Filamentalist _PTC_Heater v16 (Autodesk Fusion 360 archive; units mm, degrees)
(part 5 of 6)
sketch "Sketch194" plane through (0, 131.7787, 0) normal (0, 1, 0) x axis (-1, 0, 0)
  line L1 (37.9432, -245.7462) -> (-88.2868, -245.7462)
  line L2 (42.9432, -224.8703) -> (42.9432, -240.7462)
  line L3 (45.9432, 73.7538) -> (45.9432, -216.7462)
  line L4 (42.9432, 97.7538) -> (42.9432, 81.8778)
  line L5 (-88.2868, 102.7538) -> (37.9432, 102.7538)
  line L6 (-93.2868, 81.8778) -> (-93.2868, 97.7538)
  line L7 (-96.2868, -216.7462) -> (-96.2868, 73.7538)
  line L8 (-93.2868, -240.7462) -> (-93.2868, -224.8703)
  line L9 (-58.5552, 56.4579) -> (-62.7987, 60.7014)
  line L10 (-62.7986, 22.0143) -> (-58.5552, 26.2578)
  line L11 (-70.3955, 44.8573) -> (-70.3955, 37.8584)
  line L12 (-36.847, 36.1073) -> (-32.5999, 31.8602)
  line L13 (-32.5999, 50.8555) -> (-36.847, 46.6084)
  line L14 (-52.9532, 30.5022) -> (-57.1974, 26.258)
  line L15 (-28.3553, 26.258) -> (-32.5995, 30.5022)
  line L16 (-31.9207, 31.181) -> (-27.6765, 26.9368)
  line L17 (-27.6764, 55.779) -> (-31.9207, 51.5347)
  line L18 (-38.206, 36.1087) -> (-42.7763, 40.6791)
  line L19 (-42.7763, 40.6791) -> (-47.3467, 36.1087)
  line L20 (-57.1975, 56.4578) -> (-52.9532, 52.2135)
  line L21 (-32.5995, 52.2135) -> (-28.3552, 56.4578)
  line L22 (-27.6763, 57.1367) -> (-23.4328, 61.3802)
  line L23 (-62.1199, 61.3802) -> (-57.8764, 57.1367)
  line L24 (-47.3467, 46.607) -> (-42.7763, 42.0366)
  line L25 (-42.7763, 42.0366) -> (-38.206, 46.607)
  line L26 (-52.274, 51.5343) -> (-48.0269, 47.2872)
  line L27 (-37.5258, 47.2872) -> (-33.2787, 51.5343)
  line L28 (-48.0255, 36.7875) -> (-43.4551, 41.3578)
  line L29 (-43.4551, 41.3578) -> (-48.0255, 45.9282)
  line L30 (-52.9528, 31.8602) -> (-48.7057, 36.1073)
  line L31 (-48.7057, 46.6084) -> (-52.9528, 50.8555)
  line L32 (-37.5272, 45.9282) -> (-42.0976, 41.3578)
  line L33 (-42.0976, 41.3578) -> (-37.5272, 36.7875)
  line L34 (-48.0269, 35.4285) -> (-52.274, 31.1814)
  line L35 (-33.2787, 31.1814) -> (-37.5258, 35.4285)
  line L36 (-23.4328, 21.3355) -> (-27.6763, 25.579)
  line L37 (-57.8764, 25.579) -> (-62.1198, 21.3355)
  line L38 (-22.754, 60.7014) -> (-26.9975, 56.4579)
  line L39 (-26.9975, 26.2578) -> (-22.754, 22.0143)
  line L40 (-57.8762, 26.9368) -> (-53.632, 31.181)
  line L41 (-53.632, 51.5347) -> (-57.8763, 55.779)
  line L42 (42.9432, 102.7538) -> (-80.2209, 102.7538)
  line L43 (42.9432, -240.7462) -> (42.9432, 102.7538)
  line L44 (-80.2209, -240.7462) -> (42.9432, -240.7462)
  line L45 (-80.2209, 102.7538) -> (-80.2209, -240.7462)
  line L46 (-96.2868, 89.8158) -> (42.9432, 89.8158)
  line L47 (-96.2868, -204.6678) -> (-96.2868, 89.8158)
  line L48 (42.9432, -204.6678) -> (-96.2868, -204.6678)
  line L49 (42.9432, 89.8158) -> (42.9432, -204.6678)
  line L50 (42.9432, 89.8158) -> (-26.6718, 89.8158)
  line L51 (42.9432, 35.1964) -> (42.9432, 89.8158)
  line L52 (-26.6718, 35.1964) -> (42.9432, 35.1964)
  line L53 (-26.6718, 89.8158) -> (-26.6718, 35.1964)
  line L54 (-96.2868, 89.8158) -> (-26.6718, 89.8158)
  line L55 (-96.2868, 35.1964) -> (-96.2868, 89.8158)
  line L56 (-26.6718, 35.1964) -> (-96.2868, 35.1964)
  line L57 (-26.6718, 89.8158) -> (-26.6718, 35.1964)
  line L58 (74.0902, 102.7538) -> (17.2685, 102.7538)
  line L59 (74.0902, -245.7462) -> (74.0902, 102.7538)
  line L60 (17.2685, -245.7462) -> (74.0902, -245.7462)
  line L61 (17.2685, 102.7538) -> (17.2685, -245.7462)
  line L62 (-160, -71.4962) -> (74.0902, -71.4962)
  line L63 (-160, 150) -> (-160, -71.4962)
  line L64 (74.0902, 150) -> (-160, 150)
  line L65 (74.0902, -71.4962) -> (74.0902, 150)
  line L66 (74.0902, 89.8158) -> (-26.6718, 89.8158)
  line L67 (74.0902, -245.7462) -> (74.0902, 89.8158)
  line L68 (-26.6718, -245.7462) -> (74.0902, -245.7462)
  line L69 (-26.6718, 89.8158) -> (-26.6718, -245.7462)
  line L70 (-107.5093, -236.4962) -> (54.1657, -236.4962)
  line L71 (-107.5093, 93.5038) -> (-107.5093, -236.4962)
  line L72 (54.1657, 93.5038) -> (-107.5093, 93.5038)
  line L73 (54.1657, -236.4962) -> (54.1657, 93.5038)
  line L74 (-107.5093, 93.5038) -> (54.1657, -236.4962)
  line L75 (54.1657, 93.5038) -> (-107.5093, -236.4962)
  line L76 (-75.2868, 93.5038) -> (-93.2868, 93.5038)
  line L77 (-75.2868, 102.7538) -> (-75.2868, 93.5038)
  line L78 (-93.2868, 102.7538) -> (-75.2868, 102.7538)
  line L79 (-93.2868, 93.5038) -> (-93.2868, 102.7538)
  line L80 (24.9432, 93.5038) -> (42.9432, 93.5038)
  line L81 (24.9432, 102.7538) -> (24.9432, 93.5038)
  line L82 (42.9432, 102.7538) -> (24.9432, 102.7538)
  line L83 (42.9432, 93.5038) -> (42.9432, 102.7538)
  line L84 (-75.2868, 93.5038) -> (24.9432, 93.5038)
  line L85 (-75.2868, -306.4962) -> (-75.2868, 93.5038)
  line L86 (24.9432, -306.4962) -> (-75.2868, -306.4962)
  line L87 (24.9432, 93.5038) -> (24.9432, -306.4962)
  arc A1 centre (-88.2868, -240.7462) radius 5 clockwise from (-88.2868, -245.7462) to (-93.2868, -240.7462)
  arc A2 centre (37.9432, -240.7462) radius 5 clockwise from (42.9432, -240.7462) to (37.9432, -245.7462)
  arc A3 centre (47.9432, -224.8703) radius 5 clockwise from (42.9432, -224.8703) to (44.1432, -221.6206)
  arc A4 centre (38.4432, -216.7462) radius 7.5 clockwise from (45.9432, -216.7462) to (44.1432, -221.6206)
  arc A5 centre (38.4432, 73.7538) radius 7.5 clockwise from (44.1432, 78.6282) to (45.9432, 73.7538)
  arc A6 centre (47.9432, 81.8778) radius 5 clockwise from (44.1432, 78.6282) to (42.9432, 81.8778)
  arc A7 centre (37.9432, 97.7538) radius 5 clockwise from (37.9432, 102.7538) to (42.9432, 97.7538)
  arc A8 centre (-88.2868, 97.7538) radius 5 clockwise from (-93.2868, 97.7538) to (-88.2868, 102.7538)
  arc A9 centre (-98.2868, 81.8778) radius 5 clockwise from (-93.2868, 81.8778) to (-94.4868, 78.6282)
  arc A10 centre (-88.7868, 73.7538) radius 7.5 clockwise from (-96.2868, 73.7538) to (-94.4868, 78.6282)
  arc A11 centre (-88.7868, -216.7462) radius 7.5 clockwise from (-94.4868, -221.6206) to (-96.2868, -216.7462)
  arc A12 centre (-98.2868, -224.8703) radius 5 clockwise from (-94.4868, -221.6206) to (-93.2868, -224.8703)
  circle C1 centre (3.265, 1.258) radius 1.1
  circle C2 centre (-24.3297, -214.0862) radius 3.175
  circle C3 centre (-32.1307, -209.6412) radius 3.175
  circle C4 centre (-39.8297, -214.0862) radius 3.175
  circle C5 centre (-24.4318, -205.1962) radius 3.175
  circle C6 centre (-16.7002, -209.6409) radius 3.175
  circle C7 centre (-39.8297, -205.1962) radius 3.175
  circle C8 centre (-24.4318, -196.3062) radius 3.175
  circle C9 centre (-39.8297, -196.3062) radius 3.175
  circle C10 centre (-55.1992, -205.1959) radius 3.175
  circle C11 centre (-47.5287, -182.9712) radius 3.175
  circle C12 centre (-32.1023, -182.9709) radius 3.175
  circle C13 centre (-47.5287, -191.8612) radius 3.175
  circle C14 centre (-62.8982, -200.7509) radius 3.175
  circle C15 centre (-70.6297, -187.4162) radius 3.175
  circle C16 centre (-55.1992, -178.5259) radius 3.175
  circle C17 centre (-39.8013, -169.6359) radius 3.175
  circle C18 centre (-55.1992, -169.6359) radius 3.175
  circle C19 centre (-78.3287, -182.9712) radius 3.175
  circle C20 centre (-78.3287, -165.1912) radius 3.175
  circle C21 centre (-78.3287, -174.0812) radius 3.175
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  point P6 (42.9432, -240.7462)
  point P356 (42.9432, -240.7462)
  point P354 (-80.2209, 102.7538)
  point P360 (-96.2868, -204.6678)
  point P358 (42.9432, 89.8158)
  point P364 (42.9432, 35.1964)
  point P362 (-26.6718, 89.8158)
  point P367 (-96.2868, 35.1964)
  point P369 (17.2685, 102.7538)
  point P373 (74.0902, -71.4962)
  point P383 (-26.6718, -71.4962)
  point P384 (-93.2868, 93.5038)
  point P388 (42.9432, 93.5038)
  point P392 (-75.2868, 93.5038)
  point P395 (-75.2868, 93.5038)
  point P389 (24.9432, 93.5038)
  point P396 (24.9432, 93.5038)
  point P397 (-75.2868, -236.4962)
  point P398 (24.9432, -236.4962)
  point P380 (-107.5093, -236.4962)
  point P381 (-107.5093, 93.5038)
  point P385 (-75.2868, 93.5038)
  point P394 (24.9432, -306.4962)
  horizontal L42
  vertical L43
  horizontal L44
  vertical L45
  coincident P6 P356
  coincident L5 P354
  horizontal L46
  vertical L47
  horizontal L48
  vertical L49
  coincident L7 P360
  midpoint L4 P358
  horizontal L50
  vertical L51
  horizontal L52
  vertical L53
  coincident L43 P364
  midpoint L46 P362
  horizontal L54
  vertical L55
  horizontal L56
  vertical L57
  coincident L47 P367
  horizontal L58
  vertical L59
  horizontal L60
  vertical L61
  coincident L42 P369
  horizontal L62
  vertical L63
  horizontal L64
  vertical L65
  midpoint L59 P373
  horizontal L66
  vertical L67
  horizontal L68
  vertical L69
  horizontal L70
  perpendicular L70 L71
  parallel L70 L72
  parallel L71 L73
  coincident L74 P383
  coincident L75 P383
  coincident L62 P383
  coincident L69 P383
  horizontal L76
  vertical L77
  horizontal L78
  vertical L79
  coincident L72 P384
  coincident L6 P384
  horizontal L80
  vertical L81
  horizontal L82
  vertical L83
  coincident L43 P388
  coincident L72 P388
  horizontal L84
  vertical L85
  horizontal L86
  vertical L87
  coincident P392 P395
  coincident P389 P396
  coincident L85 P397
  coincident L70 P397
  coincident L87 P398
  coincident L70 P398
  dimension "d619" distance P380 P381 = 330
  dimension "d620" distance P384 P385 = 18
  dimension "d621" distance P388 P389 = 18
  dimension "d622" distance P389 P394 = 400
  dimension "d623" diameter = 5.4
  dimension "d624" diameter = 5.4
  dimension "d625" diameter = 5.4
  dimension "d626" diameter = 5.4
extrude "Extrude55" cut sketch "Sketch194" against normal blind 50
position "Position14"
sketch "Sketch195" plane through (0, 131.7787, 0) normal (0, 1, 0) x axis (-1, 0, 0)
  line L1 (37.9432, -245.7462) -> (-88.2868, -245.7462)
  line L2 (42.9432, -224.8703) -> (42.9432, -240.7462)
  line L3 (45.9432, 73.7538) -> (45.9432, -216.7462)
  line L4 (42.9432, 97.7538) -> (42.9432, 81.8778)
  line L5 (-88.2868, 102.7538) -> (37.9432, 102.7538)
  line L6 (-93.2868, 81.8778) -> (-93.2868, 97.7538)
  line L7 (-96.2868, -216.7462) -> (-96.2868, 73.7538)
  line L8 (-93.2868, -240.7462) -> (-93.2868, -224.8703)
  line L9 (-58.5552, 56.4579) -> (-62.7987, 60.7014)
  line L10 (-62.7986, 22.0143) -> (-58.5552, 26.2578)
  line L11 (-70.3955, 44.8573) -> (-70.3955, 37.8584)
  line L12 (-36.847, 36.1073) -> (-32.5999, 31.8602)
  line L13 (-32.5999, 50.8555) -> (-36.847, 46.6084)
  line L14 (-52.9532, 30.5022) -> (-57.1974, 26.258)
  line L15 (-28.3553, 26.258) -> (-32.5995, 30.5022)
  line L16 (-31.9207, 31.181) -> (-27.6765, 26.9368)
  line L17 (-27.6764, 55.779) -> (-31.9207, 51.5347)
  line L18 (-38.206, 36.1087) -> (-42.7763, 40.6791)
  line L19 (-42.7763, 40.6791) -> (-47.3467, 36.1087)
  line L20 (-57.1975, 56.4578) -> (-52.9532, 52.2135)
  line L21 (-32.5995, 52.2135) -> (-28.3552, 56.4578)
  line L22 (-27.6763, 57.1367) -> (-23.4328, 61.3802)
  line L23 (-62.1199, 61.3802) -> (-57.8764, 57.1367)
  line L24 (-47.3467, 46.607) -> (-42.7763, 42.0366)
  line L25 (-42.7763, 42.0366) -> (-38.206, 46.607)
  line L26 (-52.274, 51.5343) -> (-48.0269, 47.2872)
  line L27 (-37.5258, 47.2872) -> (-33.2787, 51.5343)
  line L28 (-48.0255, 36.7875) -> (-43.4551, 41.3578)
  line L29 (-43.4551, 41.3578) -> (-48.0255, 45.9282)
  line L30 (-52.9528, 31.8602) -> (-48.7057, 36.1073)
  line L31 (-48.7057, 46.6084) -> (-52.9528, 50.8555)
  line L32 (-37.5272, 45.9282) -> (-42.0976, 41.3578)
  line L33 (-42.0976, 41.3578) -> (-37.5272, 36.7875)
  line L34 (-48.0269, 35.4285) -> (-52.274, 31.1814)
  line L35 (-33.2787, 31.1814) -> (-37.5258, 35.4285)
  line L36 (-23.4328, 21.3355) -> (-27.6763, 25.579)
  line L37 (-57.8764, 25.579) -> (-62.1198, 21.3355)
  line L38 (-22.754, 60.7014) -> (-26.9975, 56.4579)
  line L39 (-26.9975, 26.2578) -> (-22.754, 22.0143)
  line L40 (-57.8762, 26.9368) -> (-53.632, 31.181)
  line L41 (-53.632, 51.5347) -> (-57.8763, 55.779)
  line L42 (38.4432, -217.5) -> (-85, -217.5)
  line L43 (-85, 73.7538) -> (38.4432, 73.7538)
  line L44 (24.9432, 93.5038) -> (-75.2868, 93.5038)
  line L45 (24.9432, 82.1771) -> (24.9432, 93.5038)
  line L46 (-75.2868, 82.1771) -> (24.9432, 82.1771)
  line L47 (-75.2868, 93.5038) -> (-75.2868, 82.1771)
  line L48 (-0.8286, 73.7538) -> (-85, 73.7538)
  line L49 (-85, 73.7538) -> (-85, 1.258)
  line L50 (38.4432, -124.7165) -> (-85, -124.7165)
  line L51 (38.4432, -217.5) -> (38.4432, -124.7165)
  line L52 (-85, -217.5) -> (38.4432, -217.5)
  line L53 (-85, -124.7165) -> (-85, -217.5)
  line L54 (-89, 73.7538) -> (-85, 73.7538)
  line L55 (-89, 77.7538) -> (-89, 73.7538)
  line L56 (-85, 77.7538) -> (-89, 77.7538)
  line L57 (-85, 73.7538) -> (-85, 77.7538)
  line L58 (42.4432, -221.5) -> (42.4432, -217.5)
  line L59 (38.4432, -221.5) -> (42.4432, -221.5)
  line L60 (42.4432, 77.7538) -> (-89, 77.7538)
  line L61 (42.4432, -221.5) -> (42.4432, 77.7538)
  line L62 (-89, -221.5) -> (42.4432, -221.5)
  line L63 (-89, 77.7538) -> (-89, -221.5)
  line L64 (38.4432, -124.7165) -> (-85, -124.7165)
  line L65 (-85, -120.7165) -> (38.4432, -120.7165)
  line L66 (-85, 1.258) -> (-85, 5.258)
  line L67 (-4.8286, 73.7538) -> (-0.8286, 73.7538)
  line L68 (-85, -120.7165) -> (-85, 73.7538)
  line L69 (-85, -217.5) -> (-85, -124.7165)
  line L70 (38.4432, -124.7165) -> (38.4432, -217.5)
  line L71 (38.4432, 73.7538) -> (38.4432, -120.7165)
  line L72 (-67.7764, 66.3578) -> (-17.7763, 66.3578)
  line L73 (-67.7764, 16.3579) -> (-67.7764, 66.3578)
  line L74 (-17.7763, 16.3579) -> (-67.7764, 16.3579)
  line L75 (-17.7763, 66.3578) -> (-17.7763, 16.3579)
  line L76 (-67.7764, 16.3579) -> (-17.7763, 66.3578)
  line L77 (-17.7763, 16.3579) -> (-67.7764, 66.3578)
  line L78 (-85, 73.7538) -> (-4.8286, 73.7538)
  line L79 (-85, 5.258) -> (-85, 73.7538)
  line L80 (-4.8286, 5.258) -> (-85, 5.258)
  line L81 (-4.8286, 73.7538) -> (-4.8286, 5.258)
  line L82 (-85, 73.7538) -> (-0.8286, 73.7538)
  line L83 (-85, 1.258) -> (-85, 73.7538)
  line L84 (-0.8286, 1.258) -> (-85, 1.258)
  line L85 (-0.8286, 73.7538) -> (-0.8286, 1.258)
  circle C1 centre (-75.2868, -236.4962) radius 2.7
  circle C2 centre (-75.2868, 93.5038) radius 2.7
  circle C3 centre (24.9432, -236.4962) radius 2.7
  circle C4 centre (24.9432, 93.5038) radius 2.7
  arc A1 centre (-88.2868, -240.7462) radius 5 clockwise from (-88.2868, -245.7462) to (-93.2868, -240.7462)
  arc A2 centre (37.9432, -240.7462) radius 5 clockwise from (42.9432, -240.7462) to (37.9432, -245.7462)
  arc A3 centre (47.9432, -224.8703) radius 5 clockwise from (42.9432, -224.8703) to (44.1432, -221.6206)
  arc A4 centre (38.4432, -216.7462) radius 7.5 clockwise from (45.9432, -216.7462) to (44.1432, -221.6206)
  arc A5 centre (38.4432, 73.7538) radius 7.5 clockwise from (44.1432, 78.6282) to (45.9432, 73.7538)
  arc A6 centre (47.9432, 81.8778) radius 5 clockwise from (44.1432, 78.6282) to (42.9432, 81.8778)
  arc A7 centre (37.9432, 97.7538) radius 5 clockwise from (37.9432, 102.7538) to (42.9432, 97.7538)
  arc A8 centre (-88.2868, 97.7538) radius 5 clockwise from (-93.2868, 97.7538) to (-88.2868, 102.7538)
  arc A9 centre (-98.2868, 81.8778) radius 5 clockwise from (-93.2868, 81.8778) to (-94.4868, 78.6282)
  arc A10 centre (-88.7868, 73.7538) radius 7.5 clockwise from (-96.2868, 73.7538) to (-94.4868, 78.6282)
  arc A11 centre (-88.7868, -216.7462) radius 7.5 clockwise from (-94.4868, -221.6206) to (-96.2868, -216.7462)
  arc A12 centre (-98.2868, -224.8703) radius 5 clockwise from (-94.4868, -221.6206) to (-93.2868, -224.8703)
  circle C5 centre (3.265, 1.258) radius 1.1
  circle C6 centre (-24.3297, -214.0862) radius 3.175
  circle C7 centre (-32.1307, -209.6412) radius 3.175
  circle C8 centre (-39.8297, -214.0862) radius 3.175
  circle C9 centre (-24.4318, -205.1962) radius 3.175
  circle C10 centre (-16.7002, -209.6409) radius 3.175
  circle C11 centre (-39.8297, -205.1962) radius 3.175
  circle C12 centre (-24.4318, -196.3062) radius 3.175
  circle C13 centre (-39.8297, -196.3062) radius 3.175
  circle C14 centre (-55.1992, -205.1959) radius 3.175
  circle C15 centre (-47.5287, -182.9712) radius 3.175
  circle C16 centre (-32.1023, -182.9709) radius 3.175
  circle C17 centre (-47.5287, -191.8612) radius 3.175
  circle C18 centre (-62.8982, -200.7509) radius 3.175
  circle C19 centre (-70.6297, -187.4162) radius 3.175
  circle C20 centre (-55.1992, -178.5259) radius 3.175
  circle C21 centre (-39.8013, -169.6359) radius 3.175
  circle C22 centre (-55.1992, -169.6359) radius 3.175
  circle C23 centre (-78.3287, -182.9712) radius 3.175
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  point P19 (38.4432, 73.7538)
  point P360 (38.4432, 73.7538)
  point P3 (-75.2868, 93.5038)
  point P362 (-75.2868, 93.5038)
  point P368 (-85, -124.7165)
  point P390 (-42.7763, 41.3579)
  point P310 (-17.7763, 66.3578)
  point P386 (-17.7763, 66.3578)
  point P385 (-42.7763, 41.3579)
  point P391 (-17.7763, 66.3578)
  point P389 (-17.7763, 16.3579)
  point P392 (-17.7763, 16.3579)
  point P388 (-67.7764, 16.3579)
  point P393 (-67.7764, 16.3579)
  point P396 (-17.7763, 16.3579)
  point P361 (-85, 73.7538)
  point P371 (-89, 73.7538)
  point P373 (-85, 77.7538)
  point P359 (38.4432, -217.5)
  point P374 (42.4432, -217.5)
  point P376 (38.4432, -221.5)
  point P381 (-85, -120.7165)
  point P367 (-85, 1.258)
  point P382 (-85, 5.258)
  point P366 (-0.8286, 73.7538)
  point P383 (-4.8286, 73.7538)
  horizontal L42
  vertical L70
  horizontal L43
  vertical L68
  coincident P19 P360
  horizontal L44
  vertical L45
  horizontal L46
  vertical L47
  coincident P3 P362
  horizontal L48
  vertical L49
  horizontal L50
  vertical L51
  horizontal L52
  vertical L53
  coincident P368 L68
  horizontal L54
  vertical L55
  horizontal L56
  vertical L57
  vertical L58
  horizontal L59
  horizontal L60
  vertical L61
  horizontal L62
  vertical L63
  horizontal L64
  horizontal L65
  vertical L66
  horizontal L67
  collinear L68 L69
  collinear L70 L71
  horizontal L72
  perpendicular L72 L73
  parallel L72 L74
  parallel L73 L75
  coincident L76 P390
  coincident L77 P390
  coincident P310 P386
  coincident P385 P390
  coincident P386 P391
  coincident P389 P392
  coincident P388 P393
  coincident P389 P396
  horizontal L78
  vertical L79
  horizontal L80
  vertical L81
  horizontal L82
  vertical L83
  horizontal L84
  vertical L85
  dimension "d629" distance P361 P371 = 4
  dimension "d630" distance P361 P373 = 4
  dimension "d631" distance P359 P374 = 4
  dimension "d632" distance P359 P376 = 4
  dimension "d633" distance P368 P381 = 4
  dimension "d634" distance P367 P382 = 4
  dimension "d635" distance P366 P383 = 4
  dimension "d636" diameter = 8.4
  dimension "d637" diameter = 8.4
  dimension "d638" diameter = 8.4
  dimension "d639" diameter = 8.4
extrude "Extrude59" new body sketch "Sketch195" along normal blind 7.5
delete_face "DeleteFace2"
fillet "Fillet2" radius 10
fillet "Fillet3" radius 5
fillet "Fillet4" radius 12
fillet "Fillet5" radius 10
sketch "Sketch196" plane through (0, 139.2787, 0) normal (0, 1, 0) x axis (-1, 0, 0)
  line L1 (-0.8286, 63.7538) -> (-0.8286, 13.258)
  line L2 (28.4432, 73.7538) -> (9.1714, 73.7538)
  line L3 (38.4432, -110.7165) -> (38.4432, 63.7538)
  line L4 (-75, -120.7165) -> (28.4432, -120.7165)
  line L5 (-85, -8.742) -> (-85, -110.7165)
  line L6 (-12.8286, 1.258) -> (-75, 1.258)
  line L7 (-85, -134.7165) -> (-85, -207.5)
  line L8 (28.4432, -124.7165) -> (-75, -124.7165)
  line L9 (38.4432, -207.5) -> (38.4432, -134.7165)
  line L10 (-75, -217.5) -> (28.4432, -217.5)
  line L11 (-14.8286, 73.7538) -> (-75, 73.7538)
  line L12 (-4.8286, 15.258) -> (-4.8286, 63.7538)
  line L13 (-75, 5.258) -> (-14.8286, 5.258)
  line L14 (-85, 63.7538) -> (-85, 15.258)
  line L15 (37.4432, -221.5) -> (-84, -221.5)
  line L16 (42.4432, 72.7538) -> (42.4432, -216.5)
  line L17 (-84, 77.7538) -> (37.4432, 77.7538)
  line L18 (-89, -216.5) -> (-89, 72.7538)
  line L19 (28.4432, 77.7538) -> (19.4287, 77.7538)
  line L20 (28.4432, 73.7538) -> (28.4432, 77.7538)
  line L21 (19.4287, 73.7538) -> (28.4432, 73.7538)
  line L22 (19.4287, 77.7538) -> (19.4287, 73.7538)
  line L23 (42.4432, 57.2957) -> (38.4432, 57.2957)
  line L24 (42.4432, 48.2332) -> (42.4432, 57.2957)
  line L25 (38.4432, 48.2332) -> (42.4432, 48.2332)
  line L26 (38.4432, 57.2957) -> (38.4432, 48.2332)
  line L27 (-65, -217.5) -> (-71, -217.5)
  line L28 (-65, -221.5) -> (-65, -217.5)
  line L29 (-71, -221.5) -> (-65, -221.5)
  line L30 (-71, -217.5) -> (-71, -221.5)
  line L31 (-85, -201) -> (-89, -201)
  line L32 (-85, -207) -> (-85, -201)
  line L33 (-89, -207) -> (-85, -207)
  line L34 (-89, -201) -> (-89, -207)
  line L35 (-63.4732, -120.7165) -> (-70.1474, -120.7165)
  line L36 (-63.4732, -124.7165) -> (-63.4732, -120.7165)
  line L37 (-70.1474, -124.7165) -> (-63.4732, -124.7165)
  line L38 (-70.1474, -120.7165) -> (-70.1474, -124.7165)
  line L39 (-46.3683, 5.258) -> (-55.4988, 5.258)
  line L40 (-46.3683, 1.258) -> (-46.3683, 5.258)
  line L41 (-55.4988, 1.258) -> (-46.3683, 1.258)
  line L42 (-55.4988, 5.258) -> (-55.4988, 1.258)
  line L43 (40.4432, 75.7538) -> (19.4287, 75.7538)
  line L44 (40.4432, 57.2957) -> (40.4432, 75.7538)
  line L45 (19.4287, 57.2957) -> (40.4432, 57.2957)
  line L46 (19.4287, 75.7538) -> (19.4287, 57.2957)
  line L47 (-71, -201) -> (-87, -201)
  line L48 (-71, -219.5) -> (-71, -201)
  line L49 (-87, -219.5) -> (-71, -219.5)
  line L50 (-87, -201) -> (-87, -219.5)
  line L51 (40.4432, -219.5) -> (-87, -219.5)
  line L52 (40.4432, 75.7538) -> (40.4432, -219.5)
  line L53 (-87, 75.7538) -> (40.4432, 75.7538)
  line L54 (-87, -219.5) -> (-87, 75.7538)
  line L55 (-46.3683, 75.7538) -> (-87, 75.7538)
  line L56 (-46.3683, 3.258) -> (-46.3683, 75.7538)
  line L57 (-87, 75.7538) -> (-87, 3.258)
  line L58 (-87, -115) -> (-87, -122.7165)
  line L59 (-70.1474, -115) -> (-87, -115)
  line L60 (-70.1474, -122.7165) -> (-70.1474, -115)
  line L61 (40.4432, -178.5523) -> (40.4432, -122.7165)
  line L62 (-87, -178.5523) -> (40.4432, -178.5523)
  line L63 (-87, -122.7165) -> (-87, -178.5523)
  line L64 (28.443, 63.753) -> (-75.0066, 63.753)
  line L65 (-2.8286, 77.7538) -> (-2.8286, 63.753)
  line L66 (40.4432, -122.7165) -> (28.4432, -110.7166)
  line L67 (28.4432, -134.7166) -> (40.4432, -122.7165)
  line L68 (-87, -122.7165) -> (-74.9306, -111.1407)
  line L69 (-87, -122.7165) -> (-75.0091, -135.3352)
  line L70 (-83.3532, 72.138) -> (-74.9907, 63.7704)
  line L71 (-84, 75.7538) -> (-87, 75.7538)
  line L72 (-84, 74.9011) -> (-84, 75.7538)
  line L73 (-87, 72.7538) -> (-86.1057, 72.7538)
  line L74 (-87, 75.7538) -> (-87, 72.7538)
  line L75 (37.4432, -219.5) -> (40.4432, -219.5)
  line L76 (40.4432, -219.5) -> (40.4432, -216.5)
  line L77 (36.9309, -218.4885) -> (28.4432, -210.0013)
  line L78 (36.7873, -218.3449) -> (28.4432, -210.0013)
  line L79 (37.9893, 73.3188) -> (-82.8642, 73.3188)
  line L80 (-82.8529, -219.547) -> (36.2894, -219.547)
  line L81 (40.4432, -122.7165) -> (38.6285, -122.7165)
  line L82 (37.9893, -121.3894) -> (37.9893, 73.3188)
  line L83 (37.9893, -217.847) -> (37.9893, -124.0462)
  line L84 (36.9285, -121.0178) -> (36.9285, -119.2018)
  line L85 (36.9285, -126.2313) -> (36.9285, -124.4178)
  line L86 (-85.1919, -122.7165) -> (-87, -122.7165)
  line L87 (35.2285, -122.7165) -> (-81.7939, -122.7165)
  line L88 (-84.5529, -123.9864) -> (-84.5529, -217.8469)
  line L89 (-81.7939, -122.7165) -> (-70.1474, -122.7165)
  line L90 (-87, -122.7165) -> (-85.1919, -122.7165)
  line L91 (-83.4529, -120.9578) -> (-83.4134, -119.2766)
  line L92 (-83.5789, -126.3167) -> (-83.5329, -124.3568)
  line L93 (-85.7308, 74.4837) -> (-87, 75.7538)
  line L94 (-75.0066, 63.753) -> (-83.37, 72.1215)
  line L95 (-82.8528, 3.258) -> (-46.3683, 3.258)
  line L96 (-87, 3.258) -> (-86.2528, 3.258)
  line L97 (-84.5529, 1.558) -> (-84.5529, -121.3282)
  line L98 (-84.5529, 71.6489) -> (-84.5529, 4.958)
  line L99 (37.9893, -219.5469) -> (-84.5529, -219.5469)
  line L100 (37.9893, -217.2726) -> (37.9893, -219.5469)
  line L101 (-84.5529, -217.2726) -> (37.9893, -217.2726)
  line L102 (-84.5529, -219.5469) -> (-84.5529, -217.2726)
  arc A1 centre (-12.8286, 13.258) radius 12 clockwise from (-0.8286, 13.258) to (-12.8286, 1.258)
  arc A2 centre (9.1714, 63.7538) radius 10 clockwise from (-0.8286, 63.7538) to (9.1714, 73.7538)
  arc A3 centre (28.4432, 63.7538) radius 10 clockwise from (28.4432, 73.7538) to (38.4432, 63.7538)
  arc A4 centre (28.4432, -110.7165) radius 10 clockwise from (38.4432, -110.7165) to (28.4432, -120.7165)
  arc A5 centre (-75, -110.7165) radius 10 clockwise from (-75, -120.7165) to (-85, -110.7165)
  arc A6 centre (-75, -8.742) radius 10 clockwise from (-85, -8.742) to (-75, 1.258)
  arc A7 centre (-75, -134.7165) radius 10 clockwise from (-85, -134.7165) to (-75, -124.7165)
  arc A8 centre (28.4432, -134.7165) radius 10 clockwise from (28.4432, -124.7165) to (38.4432, -134.7165)
  arc A9 centre (28.4432, -207.5) radius 10 clockwise from (38.4432, -207.5) to (28.4432, -217.5)
  arc A10 centre (-75, -207.5) radius 10 clockwise from (-75, -217.5) to (-85, -207.5)
  arc A11 centre (-14.8286, 63.7538) radius 10 clockwise from (-14.8286, 73.7538) to (-4.8286, 63.7538)
  arc A12 centre (-14.8286, 15.258) radius 10 clockwise from (-4.8286, 15.258) to (-14.8286, 5.258)
  arc A13 centre (-75, 15.258) radius 10 clockwise from (-75, 5.258) to (-85, 15.258)
  arc A14 centre (-75, 63.7538) radius 10 clockwise from (-85, 63.7538) to (-75, 73.7538)
  arc A15 centre (-84, -216.5) radius 5 clockwise from (-84, -221.5) to (-89, -216.5)
  arc A16 centre (37.4432, -216.5) radius 5 clockwise from (42.4432, -216.5) to (37.4432, -221.5)
  arc A17 centre (37.4432, 72.7538) radius 5 clockwise from (37.4432, 77.7538) to (42.4432, 72.7538)
  arc A18 centre (-84, 72.7538) radius 5 clockwise from (-89, 72.7538) to (-84, 77.7538)
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  point P8 (28.4432, 73.7538)
  point P58 (28.4432, 73.7538)
  point P56 (19.4287, 77.7538)
  point P62 (42.4432, 48.2332)
  point P60 (38.4432, 57.2957)
  point P66 (-65, -221.5)
  point P64 (-71, -217.5)
  point P70 (-85, -207)
  point P68 (-89, -201)
  point P74 (-63.4732, -124.7165)
  point P72 (-70.1474, -120.7165)
  point P78 (-46.3683, 1.258)
  point P76 (-55.4988, 5.258)
  point P82 (40.4432, 57.2957)
  point P80 (19.4287, 75.7538)
  point P86 (-71, -219.5)
  point P84 (-87, -201)
  point P91 (-46.3683, 3.258)
  point P95 (-87, -115)
  point P93 (-70.1474, -122.7165)
  point P108 (40.4432, -178.5523)
  point P118 (28.443, 63.753)
  point P120 (28.443, 63.753)
  point P121 (-2.8286, 63.753)
  point P103 (28.4432, -110.7166)
  point P122 (28.4432, -110.7166)
  point P113 (28.4432, -134.7166)
  point P123 (28.4432, -134.7166)
  point P124 (36.9285, -119.2018)
  point P125 (36.9285, -126.2313)
  point P115 (-74.9306, -111.1407)
  point P127 (-74.9306, -111.1407)
  point P102 (-75.0091, -135.3352)
  point P128 (-75.0091, -135.3352)
  point P129 (-83.4134, -119.2766)
  point P130 (-83.5789, -126.3167)
  point P105 (28.4432, -210.0013)
  point P137 (28.4432, -210.0013)
  point P139 (-76.2544, 75.7538)
  point P140 (-87, 65.0082)
  point P111 (28.4432, -210.0013)
  point P145 (28.4432, -210.0013)
  point P150 (-87, -209.1732)
  point P151 (-74.9931, -219.5)
  point P152 (40.4432, 63.753)
  point P153 (28.4432, 75.7532)
  point P154 (-2.8286, 77.7538)
  point P126 (36.9285, -122.7178)
  point P131 (-83.4929, -122.6573)
  point P155 (37.9893, 73.3188)
  point P175 (37.9893, 73.3188)
  point P176 (-2.8286, 73.3188)
  point P187 (37.9893, -217.2726)
  point P177 (-84.5529, -219.5469)
  point P185 (-84.5529, -219.5469)
  point P189 (37.9893, -217.2726)
  point P190 (-82.8535, -219.5)
  point P188 (-84.5529, -217.2726)
  point P191 (-84.5529, -217.2726)
  point P132 (-74.9907, 63.7704)
  point P138 (-84.5342, 73.3188)
  point P89 (-87, 75.7538)
  point P133 (-84, 75.7538)
  point P134 (-87, 72.7538)
  point P88 (40.4432, -219.5)
  point P135 (37.4432, -219.5)
  point P136 (40.4432, -216.5)
  point P146 (37.9894, -219.547)
  horizontal L19
  vertical L20
  horizontal L21
  vertical L22
  coincident P8 P58
  coincident L17 P56
  horizontal L23
  vertical L24
  horizontal L25
  vertical L26
  coincident L16 P62
  coincident L3 P60
  horizontal L27
  vertical L28
  horizontal L29
  vertical L30
  coincident L15 P66
  coincident L10 P64
  horizontal L31
  vertical L32
  horizontal L33
  vertical L34
  coincident L7 P70
  coincident L18 P68
  horizontal L35
  vertical L36
  horizontal L37
  vertical L38
  coincident L8 P74
  coincident L4 P72
  horizontal L39
  vertical L40
  horizontal L41
  vertical L42
  coincident L6 P78
  coincident L13 P76
  horizontal L43
  vertical L44
  horizontal L45
  vertical L46
  midpoint L23 P82
  midpoint L22 P80
  horizontal L47
  vertical L48
  horizontal L49
  vertical L50
  midpoint L30 P86
  midpoint L31 P84
  horizontal L51
  vertical L52
  horizontal L53
  vertical L54
  horizontal L55
  vertical L56
  horizontal L95
  vertical L57
  midpoint L40 P91
  horizontal L89
  vertical L58
  horizontal L59
  vertical L60
  coincident L54 P95
  midpoint L38 P93
  horizontal L86
  vertical L61
  horizontal L62
  vertical L63
  coincident L52 P108
  coincident P118 P120
  horizontal L64
  coincident L64 P121
  perpendicular L17 L65
  coincident P103 P122
  coincident P113 P123
  perpendicular L66 L67
  coincident L66 P124
  coincident L67 P125
  vertical L84
  coincident P115 P127
  coincident P102 P128
  coincident L68 P129
  coincident L69 P130
  parallel L70 L93
  horizontal L71
  vertical L72
  horizontal L73
  vertical L74
  horizontal L75
  vertical L76
  coincident P105 P137
  coincident L53 P139
  coincident L54 P140
  coincident P111 P145
  parallel L77 L78
  coincident L50 P150
  coincident L49 P151
  coincident L44 P152
  coincident L20 P153
  coincident L17 P154
  horizontal L79
  vertical L82
  horizontal L80
  vertical L88
  collinear L81 L86
  collinear L82 L83
  collinear L84 L85
  coincident P126 L84
  collinear L86 L87
  collinear L88 L97
  collinear L89 L90
  collinear L91 L92
  coincident P131 L91
  collinear L93 L94
  coincident P155 P175
  coincident L65 P176
  coincident L79 P176
  collinear L95 L96
  collinear L97 L98
  horizontal L99
  vertical L100
  horizontal L101
  vertical L102
  coincident L83 P187
  coincident P177 P185
  coincident P187 P189
  coincident L49 P190
  coincident P188 P191
  dimension "d650" diameter = 3.4
  dimension "d651" diameter = 3.4
  dimension "d652" distance P132 P138 = 13.5
  dimension "d653" distance P89 P133 = 3
  dimension "d654" distance P89 P134 = 3
  dimension "d655" distance P88 P135 = 3
  dimension "d656" distance P88 P136 = 3
  dimension "d658" diameter = 3.34
  dimension "d659" distance P145 P146 = 13.5
  dimension "d660" diameter = 3.4
  dimension "d661" diameter = 3.4
  dimension "d662" diameter = 3.4
  dimension "d663" diameter = 3.4
  dimension "d664" diameter = 3.4
  dimension "d665" diameter = 3.4
  dimension "d666" diameter = 3.4
extrude "Extrude60" cut sketch "Sketch196" against normal blind 10.04
delete_face "DeleteFace38"
delete_face "DeleteFace39"
position "Position15"
sketch "Sketch197" plane through (90.756, 0, 0) normal (-1, 0, 0) x axis (0, -1, 0)
  line L1 (-99.4384, 8.2249) -> (-99.4384, 5.7249)
  line L2 (-125.4372, 8.2249) -> (-99.4384, 8.2249)
  line L3 (-125.4372, 4.9737) -> (-125.4372, 8.2249)
  line L4 (-125.4372, -120.7751) -> (-125.4372, 4.9737)
  line L5 (-92.1884, -120.7751) -> (-125.4372, -120.7751)
  line L6 (-90.6884, 6.7249) -> (-90.6884, -119.2751)
  line L7 (-95.9384, 8.2249) -> (-92.1884, 8.2249)
  line L8 (-95.9384, 5.7249) -> (-95.9384, 8.2249)
  arc A1 centre (-92.1884, -119.2751) radius 1.5 clockwise from (-90.6884, -119.2751) to (-92.1884, -120.7751)
  arc A2 centre (-92.1884, 6.7249) radius 1.5 clockwise from (-92.1884, 8.2249) to (-90.6884, 6.7249)
  arc A3 centre (-97.6884, 5.7249) radius 1.75 clockwise from (-95.9384, 5.7249) to (-99.4384, 5.7249)
  circle C1 centre (-99.6884, -114.2751) radius 1.75
  circle C2 centre (-97.6884, 5.7249) radius 1.75
  circle C3 centre (-99.6884, -114.2751) radius 1.75
extrude "Extrude57" cut sketch "Sketch197" profile of A3 C1 C2 C3 against normal blind 16
move_face "MoveFace1"
sketch "Sketch198" plane through (0, 129.2387, 0) normal (0, -1, 0) x axis (1, 0, 0)
  line L1 (-37.5612, -150.2052) -> (-37.5612, -124.2957)
  line L2 (-43.4032, -150.2052) -> (-37.5612, -150.2052)
  line L3 (-43.4032, -177.6372) -> (-43.4032, -150.2052)
  line L4 (-37.5612, -177.6372) -> (-43.4032, -177.6372)
  line L5 (-37.5612, -207.3552) -> (-37.5612, -177.6372)
  line L6 (-43.4032, -207.3552) -> (-37.5612, -207.3552)
  line L7 (-43.4032, -216.7462) -> (-43.4032, -207.3552)
  line L8 (88.5868, -221.7062) -> (-38.4432, -221.7062)
  line L9 (93.5468, 73.7538) -> (93.5468, -216.7462)
  line L10 (-38.4432, 78.7138) -> (88.5868, 78.7138)
  line L11 (-43.4032, 55.8538) -> (-43.4032, 73.7538)
  line L12 (-40.8632, 55.8538) -> (-43.4032, 55.8538)
  line L13 (-40.8632, 22.1988) -> (-40.8632, 55.8538)
  line L14 (-43.4032, 22.1988) -> (-40.8632, 22.1988)
  line L15 (-43.4032, -63.4872) -> (-43.4032, 22.1988)
  line L16 (-37.5612, -63.4872) -> (-43.4032, -63.4872)
  line L17 (-37.5612, -93.2052) -> (-37.5612, -63.4872)
  line L18 (-43.4032, -93.2052) -> (-37.5612, -93.2052)
  line L19 (-43.4032, -120.4872) -> (-43.4032, -93.2052)
  line L20 (-37.5612, -120.4872) -> (-43.4032, -120.4872)
  line L21 (-37.5612, -121.1399) -> (-37.5612, -120.4872)
  line L22 (58.5552, 26.2578) -> (62.7986, 22.0143)
  line L23 (62.7987, 60.7014) -> (58.5552, 56.4579)
  line L24 (70.3955, 37.8584) -> (70.3955, 44.8573)
  line L25 (32.5999, 31.8602) -> (36.847, 36.1073)
  line L26 (36.847, 46.6084) -> (32.5999, 50.8555)
  line L27 (57.1974, 26.258) -> (52.9532, 30.5022)
  line L28 (32.5995, 30.5022) -> (28.3553, 26.258)
  line L29 (27.6765, 26.9368) -> (31.9207, 31.181)
  line L30 (31.9207, 51.5347) -> (27.6764, 55.779)
  line L31 (42.7763, 40.6791) -> (38.206, 36.1087)
  line L32 (47.3467, 36.1087) -> (42.7763, 40.6791)
  line L33 (52.9532, 52.2135) -> (57.1975, 56.4578)
  line L34 (28.3552, 56.4578) -> (32.5995, 52.2135)
  line L35 (23.4328, 61.3802) -> (27.6763, 57.1367)
  line L36 (57.8764, 57.1367) -> (62.1199, 61.3802)
  line L37 (42.7763, 42.0366) -> (47.3467, 46.607)
  line L38 (38.206, 46.607) -> (42.7763, 42.0366)
  line L39 (48.0269, 47.2872) -> (52.274, 51.5343)
  line L40 (33.2787, 51.5343) -> (37.5258, 47.2872)
  line L41 (43.4551, 41.3578) -> (48.0255, 36.7875)
  line L42 (48.0255, 45.9282) -> (43.4551, 41.3578)
  line L43 (48.7057, 36.1073) -> (52.9528, 31.8602)
  line L44 (52.9528, 50.8555) -> (48.7057, 46.6084)
  line L45 (42.0976, 41.3578) -> (37.5272, 45.9282)
  line L46 (37.5272, 36.7875) -> (42.0976, 41.3578)
  line L47 (52.274, 31.1814) -> (48.0269, 35.4285)
  line L48 (37.5258, 35.4285) -> (33.2787, 31.1814)
  line L49 (27.6763, 25.579) -> (23.4328, 21.3355)
  line L50 (62.1198, 21.3355) -> (57.8764, 25.579)
  line L51 (26.9975, 56.4579) -> (22.754, 60.7014)
  line L52 (22.754, 22.0143) -> (26.9975, 26.2578)
  line L53 (53.632, 31.181) -> (57.8762, 26.9368)
  line L54 (57.8763, 55.779) -> (53.632, 51.5347)
  line L55 (-36.7873, -218.3449) -> (-36.4625, -218.0201)
  arc A1 centre (-36.9285, -122.7178) radius 1.7 clockwise from (-37.5612, -121.1399) to (-37.5612, -124.2957)
  arc A2 centre (-38.4432, -216.7462) radius 4.96 clockwise from (-38.4432, -221.7062) to (-43.4032, -216.7462)
  arc A3 centre (88.5868, -216.7462) radius 4.96 clockwise from (93.5468, -216.7462) to (88.5868, -221.7062)
  arc A4 centre (88.5868, 73.7538) radius 4.96 clockwise from (88.5868, 78.7138) to (93.5468, 73.7538)
  arc A5 centre (-38.4432, 73.7538) radius 4.96 clockwise from (-43.4032, 73.7538) to (-38.4432, 78.7138)
  arc A6 centre (42.7763, 41.3579) radius 27.84 clockwise from (70.3955, 37.8584) to (62.7986, 22.0143)
  arc A7 centre (42.7764, 41.3578) radius 21.84 clockwise from (58.5552, 56.4579) to (58.5552, 26.2578)
  arc A8 centre (42.7763, 41.3579) radius 27.84 clockwise from (62.7987, 60.7014) to (70.3955, 44.8573)
  arc A9 centre (42.7763, 41.3579) radius 7.92 clockwise from (36.847, 36.1073) to (36.847, 46.6084)
  arc A10 centre (42.7764, 41.3579) radius 13.92 clockwise from (32.5999, 31.8602) to (32.5999, 50.8555)
  arc A11 centre (42.7764, 41.3578) radius 14.88 clockwise from (52.9532, 30.5022) to (32.5995, 30.5022)
  arc A12 centre (42.7763, 41.3579) radius 20.88 clockwise from (57.1974, 26.258) to (28.3553, 26.258)
  arc A13 centre (42.7764, 41.3578) radius 14.88 clockwise from (31.9207, 31.181) to (31.9207, 51.5347)
  arc A14 centre (42.7763, 41.3579) radius 20.88 clockwise from (27.6765, 26.9368) to (27.6764, 55.779)
  circle C1 centre (17.7763, 16.3578) radius 2.2
  circle C2 centre (17.7763, 66.3578) radius 2.2
  circle C3 centre (67.7763, 66.3578) radius 2.2
  arc A15 centre (42.7763, 41.3578) radius 6.96 clockwise from (47.3467, 36.1087) to (38.206, 36.1087)
  arc A16 centre (42.7763, 41.3579) radius 20.88 clockwise from (28.3552, 56.4578) to (57.1975, 56.4578)
  arc A17 centre (42.7764, 41.3578) radius 14.88 clockwise from (32.5995, 52.2135) to (52.9532, 52.2135)
  arc A18 centre (42.7764, 41.3578) radius 21.84 clockwise from (27.6763, 57.1367) to (57.8764, 57.1367)
  arc A19 centre (42.7763, 41.3579) radius 27.84 clockwise from (23.4328, 61.3802) to (62.1199, 61.3802)
  arc A20 centre (42.7763, 41.3578) radius 6.96 clockwise from (38.206, 46.607) to (47.3467, 46.607)
  arc A21 centre (42.7764, 41.3579) radius 13.92 clockwise from (33.2787, 51.5343) to (52.274, 51.5343)
  arc A22 centre (42.7763, 41.3579) radius 7.92 clockwise from (37.5258, 47.2872) to (48.0269, 47.2872)
  arc A23 centre (42.7763, 41.3578) radius 6.96 clockwise from (48.0255, 45.9282) to (48.0255, 36.7875)
  arc A24 centre (42.7764, 41.3579) radius 13.92 clockwise from (52.9528, 50.8555) to (52.9528, 31.8602)
  arc A25 centre (42.7763, 41.3579) radius 7.92 clockwise from (48.7057, 46.6084) to (48.7057, 36.1073)
  arc A26 centre (42.7763, 41.3578) radius 6.96 clockwise from (37.5272, 36.7875) to (37.5272, 45.9282)
  arc A27 centre (42.7763, 41.3579) radius 7.92 clockwise from (48.0269, 35.4285) to (37.5258, 35.4285)
  arc A28 centre (42.7764, 41.3579) radius 13.92 clockwise from (52.274, 31.1814) to (33.2787, 31.1814)
  circle C4 centre (67.7763, 16.3578) radius 2.2
  arc A29 centre (42.7763, 41.3579) radius 27.84 clockwise from (62.1198, 21.3355) to (23.4328, 21.3355)
  arc A30 centre (42.7764, 41.3578) radius 21.84 clockwise from (57.8764, 25.579) to (27.6763, 25.579)
  arc A31 centre (42.7763, 41.3579) radius 27.84 clockwise from (22.754, 22.0143) to (22.754, 60.7014)
  arc A32 centre (42.7764, 41.3578) radius 21.84 clockwise from (26.9975, 26.2578) to (26.9975, 56.4579)
  arc A33 centre (42.7763, 41.3579) radius 20.88 clockwise from (57.8763, 55.779) to (57.8762, 26.9368)
  arc A34 centre (42.7764, 41.3578) radius 14.88 clockwise from (53.632, 51.5347) to (53.632, 31.181)
  circle C5 centre (83.4929, -124.8112) radius 1.7
  arc A35 centre (8.9697, -205.1962) radius 3.175 clockwise from (8.9857, -202.0213) to (8.9857, -208.3712)
  arc A36 centre (9.0018, -205.1962) radius 3.175 clockwise from (8.9857, -208.3712) to (8.9857, -202.0213)
  arc A37 centre (8.9697, -187.4162) radius 3.175 clockwise from (8.9897, -184.2413) to (8.9897, -190.5912)
  arc A38 centre (9.0098, -187.4162) radius 3.175 clockwise from (8.9897, -190.5912) to (8.9897, -184.2413)
  arc A39 centre (1.3108, -165.1912) radius 3.175 clockwise from (1.2948, -168.3662) to (1.2659, -168.3659)
  arc A40 centre (1.2744, -165.1909) radius 3.175 clockwise from (1.2659, -168.3659) to (1.0551, -168.3583)
  arc A41 centre (1.2788, -165.1912) radius 3.175 clockwise from (1.0551, -168.3583) to (1.2948, -168.3662)
  arc A42 centre (9.0098, -151.8562) radius 3.175 clockwise from (8.9938, -155.0312) to (8.9649, -155.0309)
  arc A43 centre (8.9733, -151.8559) radius 3.175 clockwise from (8.9649, -155.0309) to (8.7541, -155.0233)
  arc A44 centre (8.9777, -151.8562) radius 3.175 clockwise from (8.7541, -155.0233) to (8.9938, -155.0312)
  arc A45 centre (8.9777, -134.0762) radius 3.175 clockwise from (8.9938, -130.9013) to (8.9938, -137.2512)
  arc A46 centre (9.0098, -134.0762) radius 3.175 clockwise from (8.9938, -137.2512) to (8.9938, -130.9013)
  arc A47 centre (1.2788, -147.4112) radius 3.175 clockwise from (1.2948, -144.2363) to (1.2948, -150.5862)
  arc A48 centre (1.3108, -147.4112) radius 3.175 clockwise from (1.2948, -150.5862) to (1.2948, -144.2363)
  arc A49 centre (8.9413, -169.6359) radius 3.175 clockwise from (8.9897, -166.4613) to (8.9613, -172.8109)
  arc A50 centre (9.0098, -169.6362) radius 3.175 clockwise from (8.9613, -172.8109) to (8.9897, -166.4613)
  arc A51 centre (1.2423, -182.9709) radius 3.175 clockwise from (1.2908, -179.7963) to (1.2624, -186.1459)
  arc A52 centre (1.3108, -182.9712) radius 3.175 clockwise from (1.2624, -186.1459) to (1.2908, -179.7963)
  arc A53 centre (1.2382, -200.7509) radius 3.175 clockwise from (1.2879, -197.5763) to (1.2611, -203.9258)
  arc A54 centre (1.3108, -200.7512) radius 3.175 clockwise from (1.2611, -203.9258) to (1.2879, -197.5763)
  arc A55 centre (8.9697, -214.0862) radius 3.175 clockwise from (8.9347, -217.261) to (8.9347, -210.9114)
  arc A56 centre (8.8997, -214.0862) radius 3.175 clockwise from (8.9347, -210.9114) to (8.9347, -217.261)
  arc A57 centre (8.9697, -196.3062) radius 3.175 clockwise from (8.9857, -193.1313) to (8.9857, -199.4812)
  arc A58 centre (9.0018, -196.3062) radius 3.175 clockwise from (8.9857, -199.4812) to (8.9857, -193.1313)
  arc A59 centre (1.3108, -174.0812) radius 3.175 clockwise from (1.2948, -177.2562) to (1.2659, -177.2559)
  arc A60 centre (1.2744, -174.0809) radius 3.175 clockwise from (1.2659, -177.2559) to (1.0551, -177.2483)
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extrude "Extrude61" cut sketch "Sketch198" profile of C5 against normal blind 18
sketch "Sketch199" plane through (0, 139.2787, 0) normal (0, 1, 0) x axis (-1, 0, 0)
  line L1 (36.4625, -218.0201) -> (36.7873, -218.3449)
  line L2 (-0.8286, 63.7538) -> (-0.8286, 13.258)
  line L3 (28.4432, 73.7538) -> (9.1714, 73.7538)
  line L4 (38.4432, -110.7165) -> (38.4432, 63.7538)
  line L5 (-75, -120.7165) -> (28.4432, -120.7165)
  line L6 (-85, -8.742) -> (-85, -110.7165)
  line L7 (-12.8286, 1.258) -> (-75, 1.258)
  line L8 (-85, -134.7165) -> (-85, -207.5)
  line L9 (28.4432, -124.7165) -> (-75, -124.7165)
  line L10 (38.4432, -207.5) -> (38.4432, -134.7165)
  line L11 (-75, -217.5) -> (28.4432, -217.5)
  line L12 (-14.8286, 73.7538) -> (-75, 73.7538)
  line L13 (-4.8286, 15.258) -> (-4.8286, 63.7538)
  line L14 (-75, 5.258) -> (-14.8286, 5.258)
  line L15 (-85, 63.7538) -> (-85, 15.258)
  line L16 (37.4432, -221.5) -> (-84, -221.5)
  line L17 (42.4432, 72.7538) -> (42.4432, -216.5)
  line L18 (-84, 77.7538) -> (37.4432, 77.7538)
  line L19 (-89, -216.5) -> (-89, 72.7538)
  line L20 (36.9285, -122.6573) -> (-83.4929, -122.6573)
  line L21 (36.9285, -134.7165) -> (36.9285, -122.6573)
  line L22 (-83.4929, -134.7165) -> (36.9285, -134.7165)
  line L23 (-83.4929, -122.6573) -> (-83.4929, -134.7165)
  line L24 (-79.4929, -122.6573) -> (-83.4929, -122.6573)
  line L25 (-79.4929, -128.6573) -> (-79.4929, -122.6573)
  line L26 (-83.4929, -128.6573) -> (-79.4929, -128.6573)
  line L27 (-83.4929, -122.6573) -> (-83.4929, -128.6573)
  line L28 (32.9285, -122.7178) -> (36.9285, -122.7178)
  line L29 (32.9285, -128.7178) -> (32.9285, -122.7178)
  line L30 (36.9285, -128.7178) -> (32.9285, -128.7178)
  line L31 (36.9285, -122.7178) -> (36.9285, -128.7178)
  line L32 (-234.7513, -130.6573) -> (75.7655, -130.6573)
  line L33 (-234.7513, -126.6573) -> (-234.7513, -130.6573)
  line L34 (75.7655, -126.6573) -> (-234.7513, -126.6573)
  line L35 (75.7655, -130.6573) -> (75.7655, -126.6573)
  line L36 (-234.7513, -126.6573) -> (75.7655, -130.6573)
  line L37 (75.7655, -126.6573) -> (-234.7513, -130.6573)
  line L38 (-19.8189, -100) -> (-85, -100)
  line L39 (-19.8189, -126.6573) -> (-19.8189, -100)
  line L40 (-85, -126.6573) -> (-19.8189, -126.6573)
  line L41 (-85, -100) -> (-85, -126.6573)
  line L42 (42.4432, -100) -> (-19.8189, -100)
  line L43 (42.4432, -126.6573) -> (42.4432, -100)
  line L44 (-19.8189, -126.6573) -> (42.4432, -126.6573)
  line L45 (-19.8189, -100) -> (-19.8189, -126.6573)
  arc A1 centre (-83.4929, -124.8112) radius 1.7 clockwise from (-82.1775, -123.7343) to (-84.8083, -123.7343)
  arc A2 centre (-83.4929, -122.6573) radius 1.7 clockwise from (-84.8083, -123.7343) to (-82.1775, -123.7343)
  circle C1 centre (37.9893, 73.3188) radius 1.7
  circle C2 centre (-84.5529, -217.2726) radius 1.7
  circle C3 centre (36.9285, -122.7178) radius 1.7
  circle C4 centre (-84.5342, 73.3188) radius 1.67
  arc A3 centre (37.9893, -217.2726) radius 1.7 clockwise from (36.4625, -218.0201) to (36.7257, -218.4098)
  arc A4 centre (37.9894, -219.547) radius 1.7 clockwise from (36.7257, -218.4098) to (36.7873, -218.3449)
  circle C5 centre (-84.5528, 3.258) radius 1.7
  arc A5 centre (-12.8286, 13.258) radius 12 clockwise from (-0.8286, 13.258) to (-12.8286, 1.258)
  arc A6 centre (9.1714, 63.7538) radius 10 clockwise from (-0.8286, 63.7538) to (9.1714, 73.7538)
  arc A7 centre (28.4432, 63.7538) radius 10 clockwise from (28.4432, 73.7538) to (38.4432, 63.7538)
  arc A8 centre (28.4432, -110.7165) radius 10 clockwise from (38.4432, -110.7165) to (28.4432, -120.7165)
  arc A9 centre (-75, -110.7165) radius 10 clockwise from (-75, -120.7165) to (-85, -110.7165)
  arc A10 centre (-75, -8.742) radius 10 clockwise from (-85, -8.742) to (-75, 1.258)
  arc A11 centre (-75, -134.7165) radius 10 clockwise from (-85, -134.7165) to (-75, -124.7165)
  arc A12 centre (28.4432, -134.7165) radius 10 clockwise from (28.4432, -124.7165) to (38.4432, -134.7165)
  arc A13 centre (28.4432, -207.5) radius 10 clockwise from (38.4432, -207.5) to (28.4432, -217.5)
  arc A14 centre (-75, -207.5) radius 10 clockwise from (-75, -217.5) to (-85, -207.5)
  arc A15 centre (-14.8286, 63.7538) radius 10 clockwise from (-14.8286, 73.7538) to (-4.8286, 63.7538)
  arc A16 centre (-14.8286, 15.258) radius 10 clockwise from (-4.8286, 15.258) to (-14.8286, 5.258)
  arc A17 centre (-75, 15.258) radius 10 clockwise from (-75, 5.258) to (-85, 15.258)
  arc A18 centre (-75, 63.7538) radius 10 clockwise from (-85, 63.7538) to (-75, 73.7538)
  arc A19 centre (-84, -216.5) radius 5 clockwise from (-84, -221.5) to (-89, -216.5)
  arc A20 centre (37.4432, -216.5) radius 5 clockwise from (42.4432, -216.5) to (37.4432, -221.5)
  arc A21 centre (37.4432, 72.7538) radius 5 clockwise from (37.4432, 77.7538) to (42.4432, 72.7538)
  arc A22 centre (-84, 72.7538) radius 5 clockwise from (-89, 72.7538) to (-84, 77.7538)
  circle C6 centre (32.9285, -128.7178) radius 1.7
  circle C7 centre (-79.4929, -128.6573) radius 1.7
  point P5 (-83.4929, -122.6573)
  point P70 (-83.4929, -122.6573)
  point P8 (36.9285, -122.7178)
  point P77 (36.9285, -122.7178)
  point P79 (32.9285, -128.7178)
  point P81 (32.9285, -128.7178)
  point P75 (-79.4929, -128.6573)
  point P82 (-79.4929, -128.6573)
  point P87 (-79.4929, -128.6573)
  point P90 (-19.8189, -126.6573)
  point P88 (-85, -100)
  point P93 (42.4432, -126.6573)
  point P74 (-79.4929, -122.6573)
  point P76 (-83.4929, -128.6573)
  point P78 (32.9285, -122.7178)
  point P80 (36.9285, -128.7178)
  point P84 (-234.7513, -130.6573)
  point P85 (-234.7513, -126.6573)
  horizontal L20
  vertical L21
  horizontal L22
  vertical L23
  coincident P5 P70
  horizontal L24
  vertical L25
  horizontal L26
  vertical L27
  horizontal L28
  vertical L29
  horizontal L30
  vertical L31
  coincident P8 P77
  coincident P79 P81
  coincident P75 P82
  horizontal L32
  perpendicular L32 L33
  parallel L32 L34
  parallel L33 L35
  coincident L36 P87
  coincident L37 P87
  coincident P82 P87
  horizontal L38
  vertical L39
  horizontal L40
  vertical L41
  coincident L34 P90
  coincident L6 P88
  horizontal L42
  vertical L43
  horizontal L44
  vertical L45
  coincident L34 P93
  coincident L17 P93
  dimension "d675" distance P70 P74 = 4
  dimension "d676" distance P70 P76 = 6
  dimension "d677" distance P77 P78 = 4
  dimension "d678" distance P77 P80 = 6
  dimension "d679" diameter C6 = 3.4
  dimension "d680" diameter C7 = 3.4
  dimension "d681" distance P84 P85 = 4
extrude "Extrude62" new body sketch "Sketch199" profile of A11 A12 L17 L19 L21 L23 L25 L26 L27 L29 L30 L31 C6 C7 L32 L34 L40 L44 against normal blind 7.5
delete_face "DeleteFace3"
delete_face "DeleteFace4"
delete_face "DeleteFace5"
delete_face "DeleteFace6"
delete_face "DeleteFace7"
delete_face "DeleteFace8"
delete_face "DeleteFace9"
offset_faces "OffsetFaces8" distance -6
delete_face "DeleteFace40"
delete_face "DeleteFace41"
combine "Combine6"
fillet "Fillet6" radius 15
